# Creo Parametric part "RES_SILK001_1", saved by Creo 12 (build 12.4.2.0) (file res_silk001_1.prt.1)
Units: Custom; MM, KILOGRAM, SECS

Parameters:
  PTC_WM_ITERATION = "0"
  PTC_WM_VERSION = "-.0"
  PTC_WM_LIFECYCLE_STATE = "In Work"
  PTC_WM_LIFECYCLE = "MO_CADDocument"
  PTC_WM_CREATED_BY = "Maximilian Roepper (Z0017RMS: MO)"
  PTC_WM_CREATED_ON = "18-Sep-26 11:36:42 AM"
  PTC_WM_MODIFIED_BY = "Maximilian Roepper (Z0017RMS: MO)"
  PTC_WM_MODIFIED_ON = "18-Sep-26 11:36:46 AM"
  PDMLINKNUMBER = "PDM000071454983"
  PTC_WM_NAME = "res_silk001_1.prt"
  PTC_WM_NUMBER = "PDM000071454983"

Other parameters: WEIGHT, WEIGHT_FACTOR, WEIGHT_ADD, _MASS_TEMP, _DIFF_TEMP, MC_ERRORS, SUPPLIER

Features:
  1. coordinate system
  2. datum plane "PRT_YZ"
  3. datum plane "PRT_XY"
  4. datum plane "PRT_XZ"
  5. coordinate system
  6. datum axis
  7. datum axis
  8. datum axis
  9. coordinate system
  10. imported feature

Other named items: PRT, SIEMENS_MO, DRW_VIEW_ORG, PRT_X, PRT_Y, PRT_Z, CS0, ROUGH_GROB

Layers: 00_STD_CSYS-KSYS, 01_STD_PLANES-EBENEN, 02_STD_AXES-ACHSEN, 03_STD_CSYS-KSYS, 24_IMPORT_FEAT-IMPORT_KE

Surfaces: 10 plane, 8 cylinder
